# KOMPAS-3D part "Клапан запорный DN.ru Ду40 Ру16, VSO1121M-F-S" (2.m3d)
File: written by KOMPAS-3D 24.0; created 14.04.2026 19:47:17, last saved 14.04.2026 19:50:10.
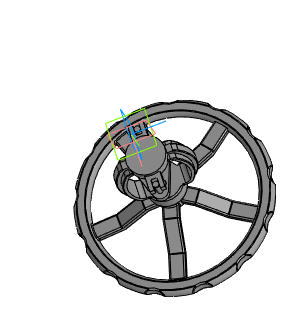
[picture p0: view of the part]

Document properties: Автор: R2D2; Полное имя файла: E:\Работа\Зайцев\VSO3131M-F-S Клапан запорный DN.ru Ду15-100 Ру16\DN40\исходные материалы\2.m3d

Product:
- Part/product: Клапан запорный DN.ru Ду40 Ру16  | designation VSO1121M-F-S
    Масса: 9.32
    Раздел спецификации: Прочие изделия
    Примечание: D090-01946

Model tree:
1. Операция без истории:1
2. Эскиз:1  (with: Ребро.Операция без истории:1)
3. Элемент вращения:1
     Угол 1 = 360
4. Эскиз:2  (with: Грань.Операция без истории:1, Ребро.Операция без истории:1)
5. Элемент выдавливания:1  (with: Грань.Операция без истории:1)
     Расстояние 1 = -27.625; Смещение 1 = 2; Расстояние 2 = -2
6. Эскиз:3  (with: Грань.Операция без истории:1, Ребро.Операция без истории:1)
7. Элемент выдавливания:2
     Расстояние 2 = 10
8. Зеркальный массив:1
9. Экземпляр ( 1 )
10. Экземпляр ( 2 )  (with: Элемент выдавливания:2)
11. Элемент выдавливания:3  (with: Грань.Элемент выдавливания:1, Грань.Элемент выдавливания:2)
     Расстояние 1 = -23.2333; Смещение 1 = 2
12. Элемент выдавливания:4  (with: Грань.Элемент выдавливания:1)  (labels: Грань.Элемент выдавливания:2.Экземпляр ( 2 ))
     Расстояние 1 = -23.2333; Смещение 1 = 2

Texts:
  VSO1121M-F-S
